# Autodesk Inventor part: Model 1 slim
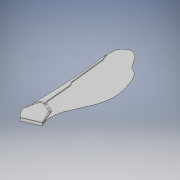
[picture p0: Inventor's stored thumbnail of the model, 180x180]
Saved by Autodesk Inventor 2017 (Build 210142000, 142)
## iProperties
Created: 2017-03
Part Number: Model 1 slim
Material: Generic
Document SubType Name: Modeling
Designer: Norris 111
Density: 1 g/cm^3
Appearance: Default
Author: Norris 111
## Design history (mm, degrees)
sketch "Sketch1"
  geometry: L1 (30.834, 66.237)-(30.834, -72.447); L2 (30.834, -72.447)-(-47.176, -72.447); L3 (-47.176, -72.447)-(-47.176, 66.237); L4 (-47.176, 66.237)-(30.834, 66.237); L5 (0, -100.183)-(0, 93.974) reference; L6 (-62.777, 0)-(46.436, 0) reference; L7 (-10.354, 25.295)-(-16.975, 22.426); 16 further points; 1 other entity
  constraints: 2 end point, 2 parallel, 25 other
  dimensions: "d12" = 138.684 distance of L1.start L1.end; "d18" = 30.8342 distance between parallel lines of L5 L1; "d23" = 72.44655 distance between parallel lines of L6 L2
extrude "Extrusion1" new body sketch "Sketch1" stored distance "d35" = 0.05; taper "d36" = 0 deg
sketch "Sketch2"
  geometry: L1 (9.696, -13.733)-(14.203, -15.48); L2 (10.354, -25.295)-(16.975, -22.426) reference; L3 (14.203, -15.48)-(16.975, -22.426); L4 (16.975, -22.426)-(14.203, -16.877); L5 (14.203, -16.877)-(10.354, -15.095); L6 (10.354, -15.095)-(9.528, -15.095); L7 (9.528, -15.095)-(8.914, -15.749); L8 (8.914, -15.749)-(8.382, -17.614); L9 (8.382, -17.614)-(7.661, -21.301); L10 (9.696, -13.733)-(8.648, -1.561); L11 (8.648, -1.561)-(7.807, -0.795); L12 (7.807, -0.795)-(6.073, 14.776); L13 (6.073, 14.776)-(5.073, 17.085); L14 (7.661, -21.301)-(7.429, -20.605); 4 further points
  constraints: 26 end point, 1 horizontal, 8 other
extrude "Extrusion2" join sketch "Sketch2" distance "d37" = 0.275; taper "d38" = 0 deg
sketch "Sketch3"
  geometry: L1 (8.382, -17.614)-(7.661, -21.301) reference; L2 (10.354, -25.295)-(16.975, -22.426) reference; L3 (16.975, -22.426)-(14.203, -16.877) reference; L4 (14.203, -16.877)-(10.354, -15.095) reference; L5 (10.354, -15.095)-(9.528, -15.095) reference; L6 (9.528, -15.095)-(8.914, -15.749) reference; L7 (8.914, -15.749)-(8.382, -17.614) reference; 1 further point
  constraints: 1 other
extrude "Extrusion3" join sketch "Sketch3" distance "d39" = 0.675; taper "d40" = 0 deg
mirror "Mirror1"
sketch "Sketch4"
  geometry: L1 (7.429, 20.605)-(7.661, 21.301) reference; 1 further point
  constraints: 1 other
extrude "Extrusion4" cut sketch "Sketch4" distance "d41" = 0.975; taper "d42" = 0 deg
fillet "Fillet1" dims "d43" = 1
fillet "Fillet2" dims "d44" = 2
fillet "Fillet3" dims "d45" = 2
fillet "Fillet5" dims "d47" = 0.125
body "Solid1"
node "Image1"
node "Projected Loop1"
node "Projected Loop2"
